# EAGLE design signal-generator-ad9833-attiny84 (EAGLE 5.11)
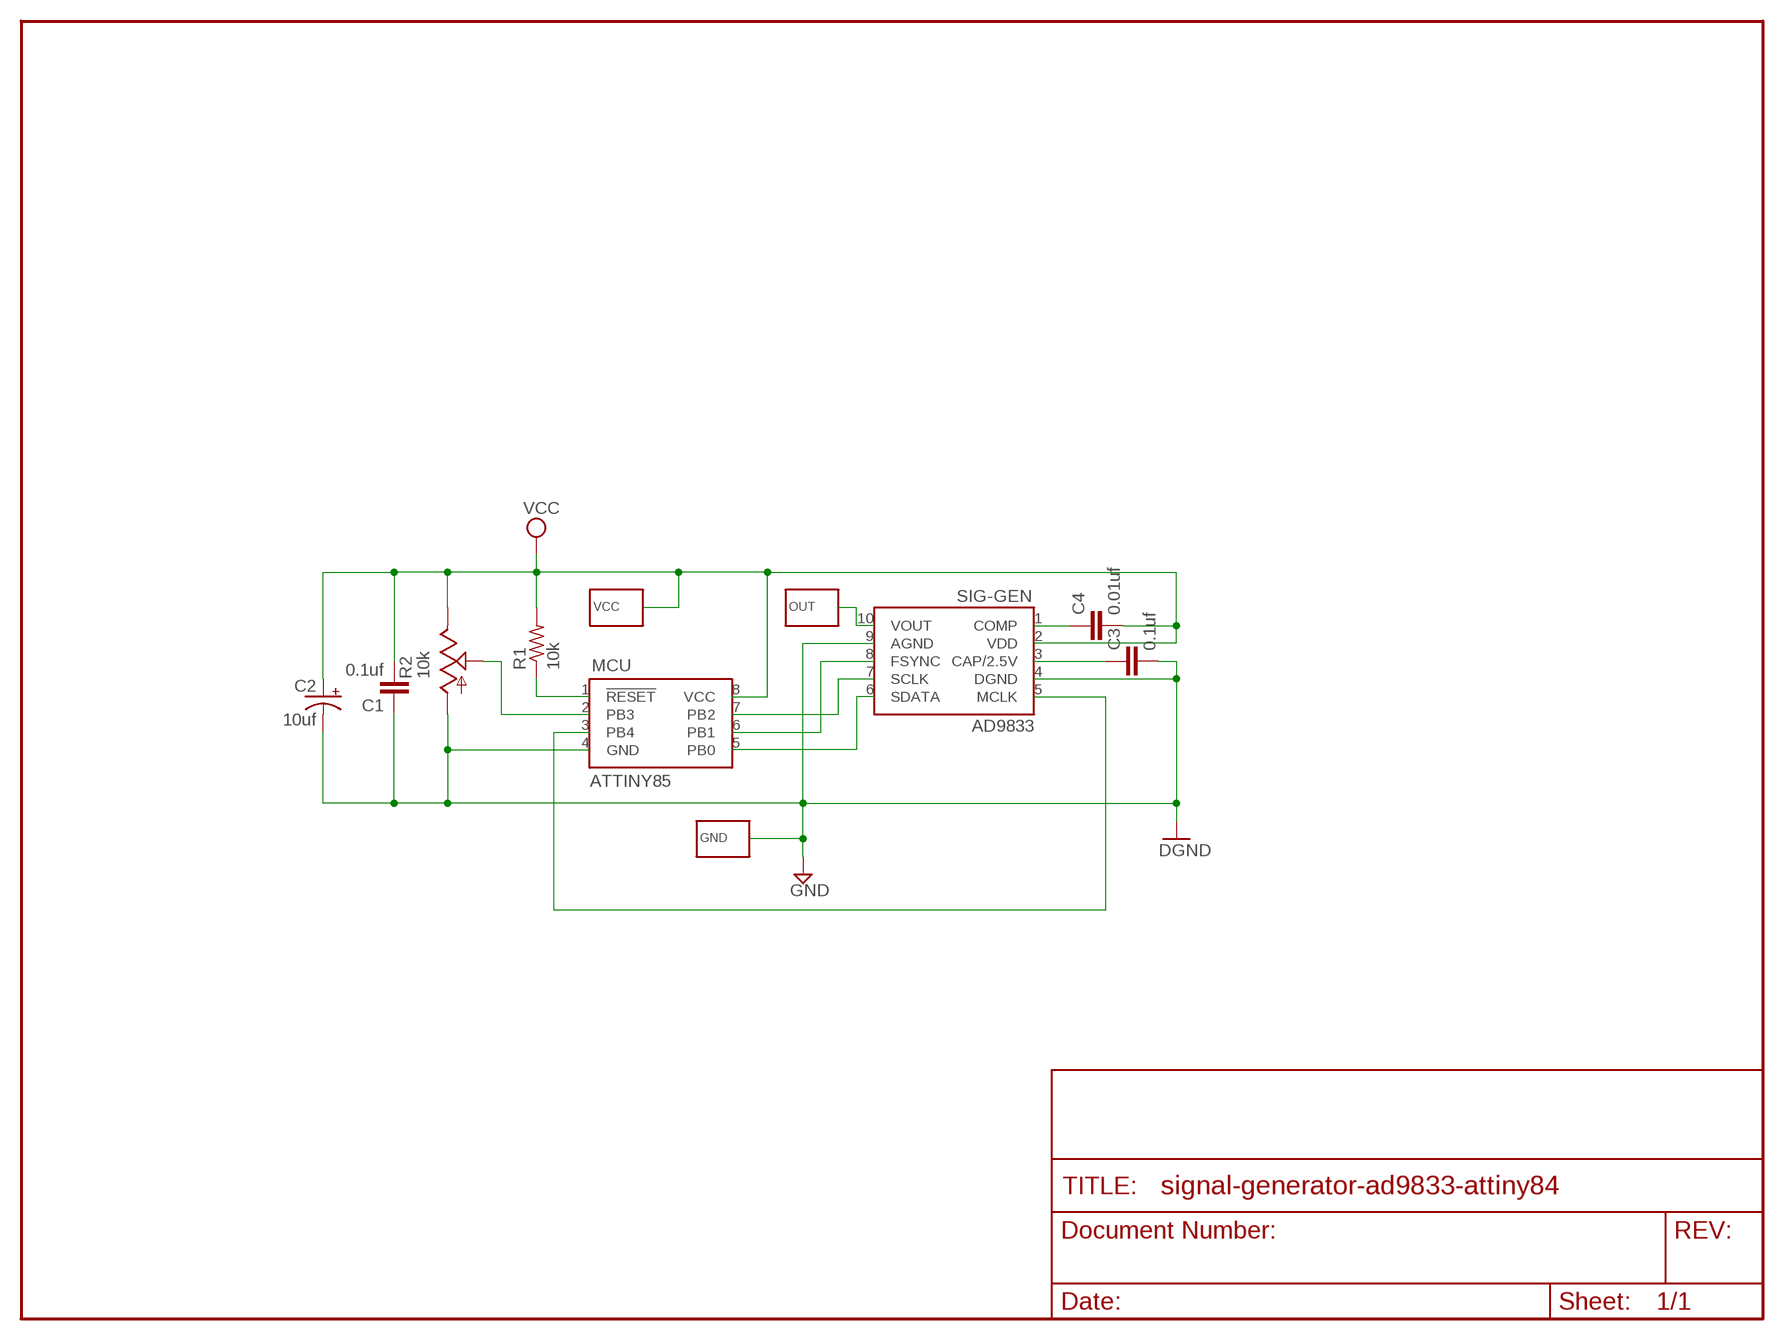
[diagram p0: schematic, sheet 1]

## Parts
C1  0.1uf  C-EUC1206  [C1206]
C2  10uf  CPOL-USE2-5  [E2-5]
C3  0.1uf  C-EUC1206  [C1206]
C4  0.01uf  C-EU050-024X044  [C050-024X044]
GND  WIREPAD-SMD-NO-VALUE  [WIREPAD-SMD]
MCU  ATTINY85  [8DIP]
OUT  WIREPAD-SMD-NO-VALUE  [WIREPAD-SMD]
R1  10k  R-US_R0603  [R0603]
R2  10k  POT-TRIM-PARALLAX  [POT-TRIM-PARALLAX]
SIG-GEN  AD9833  [10MSOP]
VCC  WIREPAD-SMD-NO-VALUE  [WIREPAD-SMD]

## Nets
GND: C1.1 C2.- C3.2 GND.1(P) MCU.4(GND) R2.1(A) SIG-GEN.4(DGND) SIG-GEN.9(AGND) ; supply symbol labelled DGND
N$1: MCU.1(!RESET) R1.1
N$2: MCU.7(PB2) SIG-GEN.7(SCLK)
N$3: MCU.3(PB4) SIG-GEN.5(MCLK)
N$4: MCU.5(PB0) SIG-GEN.6(SDATA)
N$5: MCU.6(PB1) SIG-GEN.8(FSYNC)
N$6: C3.1 SIG-GEN.3(CAP/2.5V)
N$7: MCU.2(PB3) R2.2(S)
N$8: C4.1 SIG-GEN.1(COMP)
N$9: OUT.1(P) SIG-GEN.10(VOUT)
VCC: C1.2 C2.+ C4.2 MCU.8(VCC) R1.2 R2.3(E) SIG-GEN.2(VDD) VCC.1(P)

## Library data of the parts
C1 C3 C4 = rcl:C-EU: CAPACITOR, European symbol
C2 = rcl:CPOL-US: POLARIZED CAPACITOR, American symbol
GND OUT VCC = trl:WIREPAD-SMD-NO-VALUE
MCU = trl:ATTINY85
R1 = resistor:R-US_: RESISTOR, American symbol
R2 = trl:POT-TRIM-PARALLAX: POTENTIOMETER
SIG-GEN = trl:AD9833

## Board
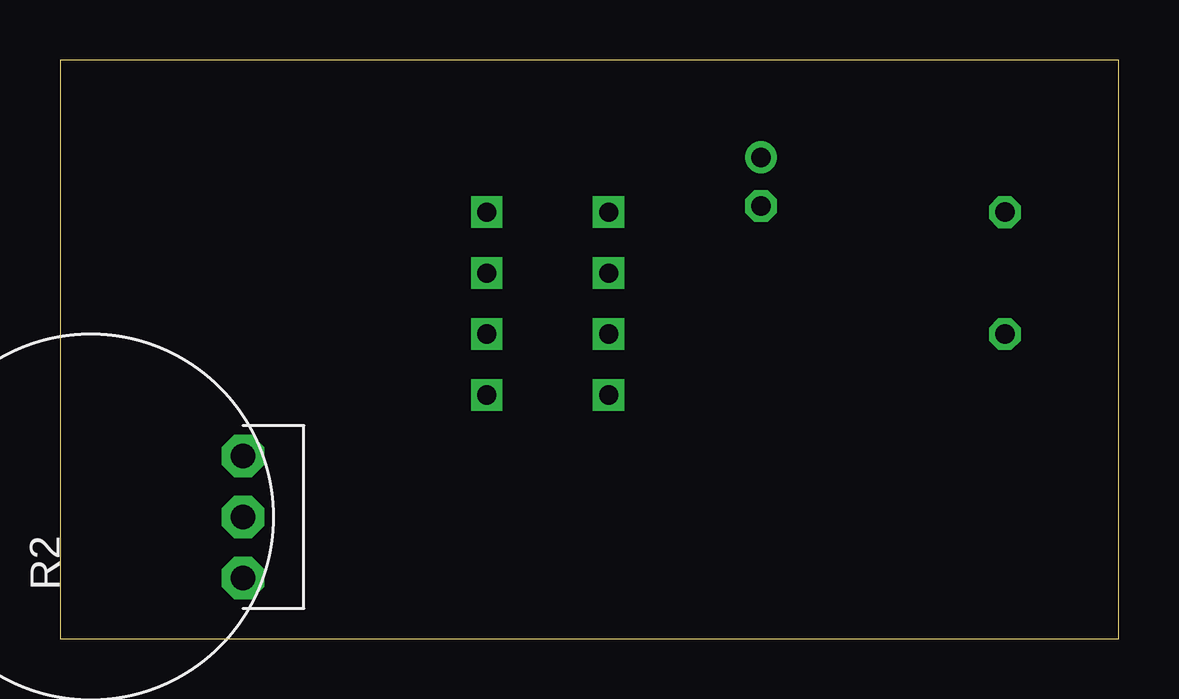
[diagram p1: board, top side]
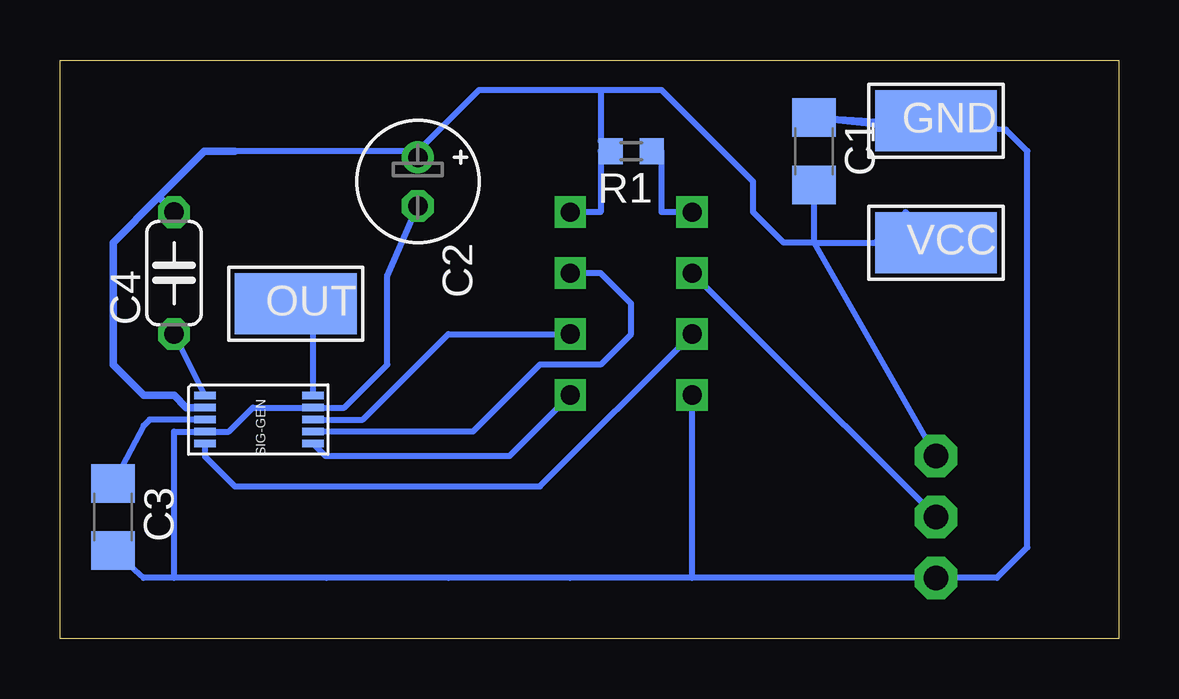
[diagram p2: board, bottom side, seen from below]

Size 44.12 x 24.12 mm. Coordinates in mm from the lower left corner, seen from the top.
Outline: 0,0 44.12,0 44.12,24.12 0,24.12 0,0
Copper layers (1*16): Top 0.035mm / dielectric 1.5mm / Bottom 0.035mm
Design rules "default": minimum track width 10mil, minimum drill 24mil, track to track 8mil, track to pad 8mil, pad to pad 8mil, via to via 8mil, smd to smd 8mil, copper to edge 40mil, drill to drill 8mil, minimum pad ring 10mil, minimum via ring 8mil, stop-mask expansion 4mil, vias tented up to drill 0mil, thermal gap 10mil

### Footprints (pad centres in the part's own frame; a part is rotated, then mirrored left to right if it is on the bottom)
C1206 = smd 1.6 x 1.8: 1 -1.4,0; 2 1.4,0
E2-5 = drill 0.813 pad 1.27 round: + -1.016,0 | drill 0.813 pad 1.27 octagon: - 1.016,0
C050-024X044 = drill 0.813 octagon: 1 -2.54,0; 2 2.54,0
WIREPAD-SMD = smd 2.54 x 5.08: 1 0,0
8DIP = drill 0.8 square: 1 -11.43,3.81; 2 -11.43,1.27; 3 -11.43,-1.27; 4 -11.43,-3.81; 5 -6.35,-3.81; 6 -6.35,-1.27; 7 -6.35,1.27; 8 -6.35,3.81
R0603 = smd 1 x 1.1: 1 -0.85,0; 2 0.85,0
POT-TRIM-PARALLAX = drill 1.016 pad 1.778 octagon: 1 -2.54,-3.81; 2 0,-3.81; 3 2.54,-3.81
10MSOP = smd 0.3 x 0.9: 1 -1.25,-5.05; 2 -0.75,-5.05; 3 -0.25,-5.05; 4 0.25,-5.05; 5 0.75,-5.05; 6 0.75,-0.55; 7 0.25,-0.55; 8 -0.25,-0.55; 9 -0.75,-0.55; 10 -1.25,-0.55

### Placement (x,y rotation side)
C1  12.7,20.32 270 bottom
C2  29.21,19.05 270 bottom
C3  41.91,5.08 270 bottom
C4  39.37,15.24 90 bottom
GND  7.62,21.59 90 bottom
MCU  29.21,13.97 0 top
OUT  34.29,13.97 90 bottom
R1  20.32,20.32 180 bottom
R2  3.81,5.08 90 top
SIG-GEN  33.02,8.89 270 bottom
VCC  7.62,16.51 90 bottom

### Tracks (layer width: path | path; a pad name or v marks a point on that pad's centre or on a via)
GND
  Bottom 0.254: 17.78,2.54 R2.1 5.08,2.54 3.81,3.81 3.81,20.32 4.71,21.22 C1.1 7.99,21.22 GND.1 | 17.78,2.54 22.86,2.54 27.94,2.54 33.02,2.54 39.37,2.54 | 17.78,2.54 MCU.4 | C3.2 40.64,2.54 39.37,2.54 | C2.- 30.48,15.11 30.48,11.43 31.75,10.16 32.27,9.64 SIG-GEN.9 36.08,9.64 36.83,8.89 37.08,8.64 SIG-GEN.4 38.35,8.64 39.37,8.64 39.37,7.62 39.37,2.54
N$1
  Bottom 0.254: MCU.1 19.05,17.78 19.05,20.32 R1.1
N$2
  Bottom 0.254: MCU.7 21.59,15.24 20.32,13.97 20.32,12.7 21.59,11.43 24.13,11.43 25.4,10.16 26.67,8.89 26.92,8.64 SIG-GEN.7
N$3
  Bottom 0.254: SIG-GEN.5 38.07,7.59 36.83,6.35 24.13,6.35 MCU.3
N$4
  Bottom 0.254: MCU.5 25.4,7.62 33.05,7.62 SIG-GEN.6
N$5
  Bottom 0.254: SIG-GEN.8 31.5,9.14 30.48,10.16 27.94,12.7 MCU.6
N$6
  Bottom 0.254: SIG-GEN.3 40.39,9.14 40.64,8.89 C3.1
N$7
  Bottom 0.254: MCU.2 15.24,12.7 R2.2
N$8
  Bottom 0.254: SIG-GEN.1 C4.1
N$9
  Bottom 0.254: SIG-GEN.10 33.57,13.25 OUT.1
VCC
  Bottom 0.254: MCU.8 21.59,17.78 21.59,20.32 R1.2 21.59,20.74 21.59,22.86 | R2.3 12.7,16.51 | 12.7,16.51 C1.2 | 12.7,16.51 10.16,16.51 8.89,17.78 VCC.1 | 36.83,20.32 29.46,20.32 C2.+ 29.21,20.32 26.67,22.86 21.59,22.86 | 12.7,16.51 13.97,16.51 15.24,17.78 15.24,19.05 19.05,22.86 21.59,22.86
  Bottom 0.305: SIG-GEN.2 38.85,9.64 39.37,10.16 40.64,10.16 41.91,11.43 41.91,16.51 40.01,18.41 | 40.01,18.41 38.1,20.32 36.83,20.32 | 40.01,18.41 C4.2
